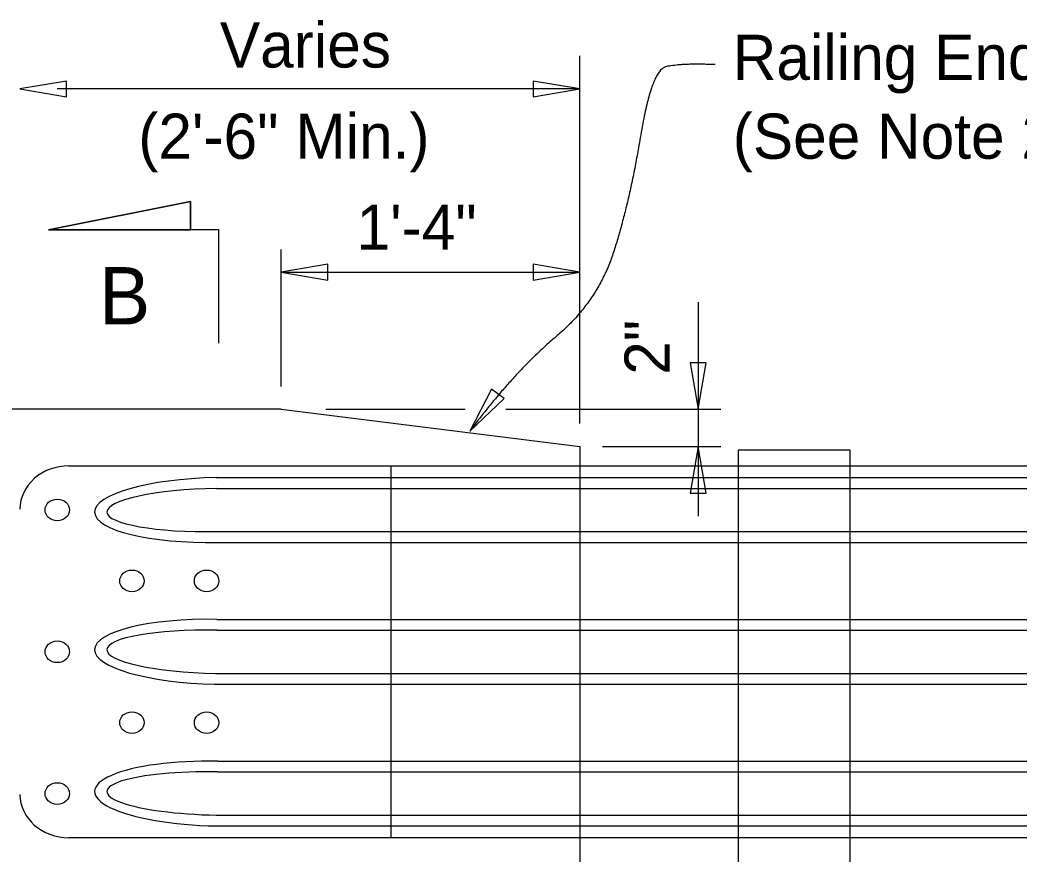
# Model space of a CAD drawing. Extents: x 0 to 41.1, y 0 to 26.
# Drawn here: x 27.706 to 32.167, y 11.855 to 15.579 of the extents above; entities that cross this region are included whole.
import ezdxf

# ---------------------------------------------------------------- set-up
doc = ezdxf.new("R2010")
doc.units = 0
for name, color, linetype in [('Dimension', 7, 'Continuous'), ('Miscellaneous', 7, 'Continuous'), ('TextStructures', 7, 'Continuous'), ('TrafBarrierConc', 7, 'Continuous')]:
    doc.layers.add(name, color=color, linetype=linetype)

# ---------------------------------------------------------------- blocks, each defined once
blk = doc.blocks.new('Terminator-Arrow')
at = {"layer": 'Dimension'}
blk.add_lwpolyline([(0, 0), (-0.0004099, 0.0000694), (-0.0004099, -0.0000694)], close=True, dxfattribs=at)

msp = doc.modelspace()

# ---------------------------------------------------------------- linework, layer by layer
at = {"layer": 'Dimension'}
for p, q in [((30.206, 13.7776), (30.206, 15.4196)), ((30.206, 15.2713), (27.8726, 15.2713)), ((27.8339, 14.6421), (28.4667, 14.7687)), ((28.4667, 14.7687), (28.4667, 14.6421)), ((28.5933, 14.6421), (27.8339, 14.6421)), ((28.5933, 14.1359), (28.5933, 14.6421)), ((28.8726, 13.9422), (28.8726, 14.5537)), ((28.8726, 14.4528), (30.2059, 14.4528)), ((30.7343, 14.3197), (30.7343, 13.3636)), ((29.0719, 13.8413), (29.6947, 13.8413)), ((29.8763, 13.8413), (30.8351, 13.8413)), ((30.3068, 13.6746), (30.8351, 13.6746))]:
    msp.add_line(p, q, dxfattribs=at)
for points in [[(27.7059, 15.2713), (27.9142, 15.236), (27.9142, 15.3066)], [(30.206, 15.2713), (29.9977, 15.3066), (29.9977, 15.236)], [(28.4667, 14.6421), (28.4667, 14.7687), (27.8339, 14.6421)], [(28.8727, 14.4528), (29.081, 14.4175), (29.081, 14.4881)], [(30.206, 14.4528), (29.9977, 14.4881), (29.9977, 14.4175)], [(29.7142, 13.7435), (29.8679, 13.8884), (29.8116, 13.9309)]]:
    msp.add_lwpolyline(points, close=True, dxfattribs=at)
msp.add_open_spline([(30.8105, 15.3797), (30.6548, 15.3862), (30.5251, 15.3537), (30.4277, 14.7629), (30.285, 14.3214), (29.9152, 14.0097), (29.7141, 13.7435)], degree=2, dxfattribs=at)
at = {"layer": 'Miscellaneous'}
for p, q in [((27.9244, 13.588), (35.096, 13.588)), ((29.3639, 11.9279), (29.3639, 13.588)), ((28.582, 13.5358), (35.096, 13.5358)), ((28.5832, 13.4876), (35.096, 13.4876)), ((28.5879, 13.2948), (35.096, 13.2948)), ((28.5891, 13.2465), (35.096, 13.2465)), ((28.5856, 12.9026), (35.096, 12.9026)), ((28.5844, 12.8543), (35.096, 12.8543)), ((28.5792, 12.6615), (35.096, 12.6615)), ((28.575, 12.6134), (35.096, 12.6134)), ((28.5891, 12.2695), (35.096, 12.2695)), ((28.5879, 12.2212), (35.096, 12.2212)), ((28.5817, 12.0284), (35.096, 12.0284)), ((28.5827, 11.9802), (35.096, 11.9802)), ((27.9244, 11.9279), (35.096, 11.9279))]:
    msp.add_line(p, q, dxfattribs=at)
msp.add_lwpolyline([(31.4128, 9.9291), (31.4128, 13.6579), (30.9128, 13.6579), (30.9128, 9.9291)], dxfattribs=at)
for centre, major_axis, ratio, start_param, end_param in [((27.9245, 13.3952), (0.2185, 0), 0.882613, 1.570796, 3.141593), ((28.5857, 13.3912), (-0.5464, -0.0102), 0.264749, 4.713933, 7.855525), ((28.5857, 13.3912), (-0.4917, -0.0093), 0.196063, 4.713495, 7.855087), ((28.5821, 12.7579), (-0.5428, 0.0103), 0.266477, 4.71081, 7.852402), ((28.5821, 12.7579), (-0.4882, 0.0094), 0.197486, 4.711258, 7.85285), ((28.5857, 12.1248), (-0.5464, 0.0102), 0.264749, 4.710845, 7.852438), ((28.5857, 12.1248), (-0.4917, 0.0093), 0.196063, 4.711283, 7.852876), ((27.9245, 12.1207), (0.2185, 0), 0.882613, 3.141593, 4.712389)]:
    msp.add_ellipse(centre, major_axis=major_axis, ratio=ratio, start_param=start_param, end_param=end_param, dxfattribs=at)
for centre in [(27.8726, 13.3912), (28.206, 13.0745), (28.5393, 13.0746), (27.8726, 12.758), (28.206, 12.4415), (28.5393, 12.4414), (27.8726, 12.1248)]:
    msp.add_ellipse(centre, major_axis=(0.0547, 0), ratio=0.882613, dxfattribs=at)
at = {"layer": 'TrafBarrierConc'}
for p, q in [((28.8726, 13.8413), (27.1859, 13.8413)), ((28.8726, 13.8413), (30.2059, 13.6746)), ((30.2059, 13.6746), (30.2059, 11.008))]:
    msp.add_line(p, q, dxfattribs=at)

# ---------------------------------------------------------------- block references
at = {"layer": 'Dimension', "xscale": 506.349, "yscale": 512.1577380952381}
for p, rotation in [((30.734, 13.8411), -90), ((30.734, 13.6744), 90)]:
    msp.add_blockref('Terminator-Arrow', p, dxfattribs=dict(at, rotation=rotation))

# ---------------------------------------------------------------- texts
at = {"layer": 'Dimension'}
for s, p in [('Railing End Transition ', (30.889, 15.3116)), ('(See Note 2)', (30.889, 14.9596))]:
    msp.add_text(s, height=0.2016, dxfattribs=at).set_placement(p)
at = {"layer": 'TextStructures'}
for s, height, p in [('Varies', 0.2016, (28.5986, 15.3668)), ('(2\'-6" Min.)', 0.2016, (28.2342, 14.9593)), ('1\'-4"', 0.2016, (29.2089, 14.5534)), ('B', 0.256, (28.0593, 14.2197))]:
    msp.add_text(s, height=height, dxfattribs=at).set_placement(p)
msp.add_text('2"', height=0.2016, rotation=90, dxfattribs=at).set_placement((30.6072, 13.9946))

doc.saveas('drawing.dxf')
